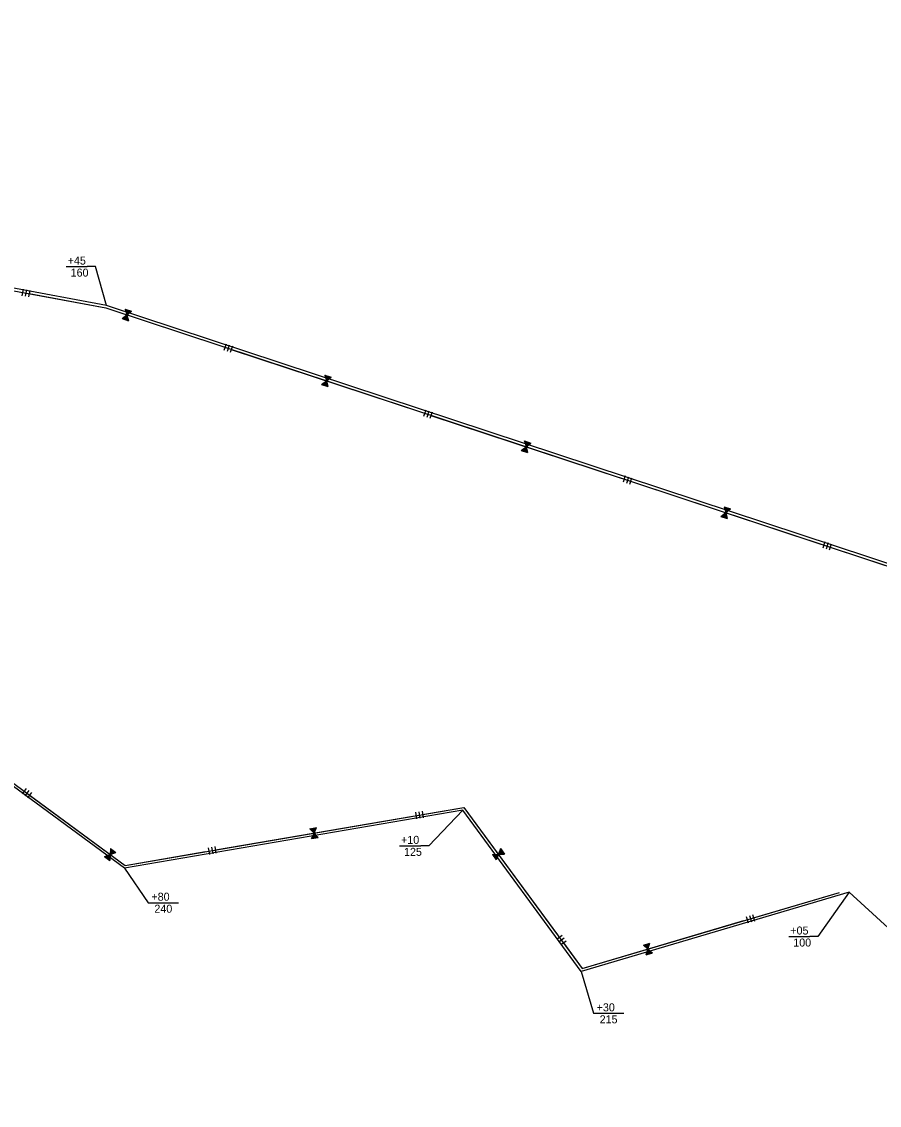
# Model space of a CAD drawing. Extents: x 979729 to 993523, y 1834148 to 1845433.
# Drawn here: x 982788 to 983431, y 1837610 to 1838423 of the extents above; entities that cross this region are included whole.
import ezdxf

# ---------------------------------------------------------------- set-up
doc = ezdxf.new("R2010")
doc.units = 0
for name, color, linetype in [('42', 7, 'Continuous'), ('51', 7, 'Continuous'), ('R_Draft', 7, 'Continuous')]:
    doc.layers.add(name, color=color, linetype=linetype)

msp = doc.modelspace()

# ---------------------------------------------------------------- linework, layer by layer
at = {"layer": '42'}
for p, q in [((982490.19, 1838275.5), (982851.26, 1838208.07)), ((982789.31, 1838222.19), (982788.4, 1838217.27)), ((982791.77, 1838221.73), (982790.85, 1838216.81)), ((982794.23, 1838221.27), (982793.31, 1838216.35)), ((982851.26, 1838208.07), (983611.03, 1837957.02)), ((982865.74, 1838207.24), (982866.94, 1838202.89)), ((982863.39, 1838200.12), (982866.94, 1838202.89)), ((982863.46, 1838200.15), (982863.48, 1838200.09)), ((982863.68, 1838200.3), (982863.77, 1838199.99)), ((982863.89, 1838200.48), (982864.05, 1838199.9)), ((982864.11, 1838200.63), (982864.34, 1838199.8)), ((982864.32, 1838200.82), (982864.62, 1838199.71)), ((982864.52, 1838201), (982864.91, 1838199.62)), ((982864.74, 1838201.15), (982865.19, 1838199.52)), ((982864.98, 1838201.23), (982865.43, 1838199.59)), ((982865.18, 1838201.46), (982865.76, 1838199.33)), ((982865.4, 1838201.6), (982866.05, 1838199.24)), ((982865.6, 1838201.82), (982866.33, 1838199.14)), ((982865.78, 1838207.17), (982865.83, 1838207.21)), ((982865.82, 1838201.94), (982866.62, 1838199.05)), ((982865.87, 1838206.92), (982866.12, 1838207.11)), ((982865.93, 1838206.65), (982866.4, 1838207.02)), ((982866.01, 1838206.4), (982866.69, 1838206.93)), ((982866.02, 1838202.15), (982866.9, 1838198.96)), ((982866.07, 1838206.12), (982866.97, 1838206.83)), ((982866.13, 1838205.85), (982867.26, 1838206.74)), ((982866.21, 1838205.6), (982867.55, 1838206.64)), ((982866.24, 1838202.3), (982867.19, 1838198.86)), ((982866.35, 1838205.39), (982867.7, 1838206.45)), ((982866.38, 1838205.1), (982868.12, 1838206.45)), ((982866.45, 1838202.48), (982867.47, 1838198.77)), ((982866.47, 1838204.85), (982868.4, 1838206.36)), ((982866.5, 1838204.56), (982868.69, 1838206.27)), ((982866.61, 1838204.33), (982868.97, 1838206.17)), ((982866.65, 1838204.04), (982869.26, 1838206.08)), ((982866.68, 1838202.6), (982867.76, 1838198.67)), ((982866.73, 1838203.79), (982869.54, 1838205.98)), ((982866.79, 1838203.51), (982869.83, 1838205.89)), ((982866.88, 1838202.82), (982868.04, 1838198.58)), ((982866.9, 1838203.28), (982870.11, 1838205.79)), ((982866.94, 1838202.99), (982870.4, 1838205.7)), ((982866.94, 1838202.89), (982870.49, 1838205.67)), ((982866.94, 1838202.89), (982868.14, 1838198.55)), ((982941.31, 1838180.95), (982939.74, 1838176.2)), ((982943.69, 1838180.17), (982942.12, 1838175.42)), ((982946.06, 1838179.38), (982944.49, 1838174.63)), ((983012.94, 1838150.7), (983016.49, 1838153.48)), ((983013.01, 1838150.73), (983013.03, 1838150.67)), ((983013.23, 1838150.88), (983013.31, 1838150.58)), ((983013.44, 1838151.07), (983013.6, 1838150.48)), ((983013.66, 1838151.21), (983013.88, 1838150.39)), ((983013.86, 1838151.4), (983014.17, 1838150.29)), ((983014.07, 1838151.59), (983014.45, 1838150.2)), ((983014.29, 1838151.73), (983014.74, 1838150.11)), ((983014.53, 1838151.82), (983014.98, 1838150.17)), ((983014.72, 1838152.04), (983015.31, 1838149.92)), ((983014.94, 1838152.19), (983015.6, 1838149.82)), ((983015.14, 1838152.4), (983015.88, 1838149.73)), ((983015.29, 1838157.82), (983016.49, 1838153.48)), ((983015.33, 1838157.75), (983015.38, 1838157.79)), ((983015.37, 1838152.52), (983016.17, 1838149.63)), ((983015.42, 1838157.5), (983015.67, 1838157.7)), ((983015.47, 1838157.23), (983015.95, 1838157.6)), ((983015.56, 1838156.98), (983016.24, 1838157.51)), ((983015.57, 1838152.73), (983016.45, 1838149.54)), ((983015.62, 1838156.71), (983016.52, 1838157.42)), ((983015.67, 1838156.44), (983016.81, 1838157.32)), ((983015.76, 1838156.19), (983017.09, 1838157.23)), ((983015.79, 1838152.88), (983016.74, 1838149.45)), ((983015.9, 1838155.98), (983017.25, 1838157.03)), ((983015.93, 1838155.68), (983017.66, 1838157.04)), ((983016, 1838153.07), (983017.02, 1838149.35)), ((983016.02, 1838155.43), (983017.95, 1838156.94)), ((983016.05, 1838155.14), (983018.23, 1838156.85)), ((983016.16, 1838154.91), (983018.52, 1838156.76)), ((983016.19, 1838154.62), (983018.8, 1838156.66)), ((983016.22, 1838153.19), (983017.31, 1838149.26)), ((983016.28, 1838154.37), (983019.09, 1838156.57)), ((983016.34, 1838154.1), (983019.37, 1838156.47)), ((983016.42, 1838153.4), (983017.59, 1838149.16)), ((983016.45, 1838153.87), (983019.66, 1838156.38)), ((983016.48, 1838153.58), (983019.94, 1838156.28)), ((983016.49, 1838153.48), (983020.04, 1838156.25)), ((983016.49, 1838153.48), (983017.69, 1838149.13)), ((983090.86, 1838131.53), (983089.29, 1838126.79)), ((983093.23, 1838130.75), (983091.67, 1838126)), ((983095.61, 1838129.97), (983094.04, 1838125.22)), ((983162.49, 1838101.28), (983166.04, 1838104.06)), ((983162.98, 1838101.65), (983163.15, 1838101.07)), ((983163.2, 1838101.8), (983163.43, 1838100.97)), ((983163.41, 1838101.99), (983163.72, 1838100.88)), ((983163.62, 1838102.17), (983164, 1838100.78)), ((983163.84, 1838102.32), (983164.29, 1838100.69)), ((983164.07, 1838102.4), (983164.53, 1838100.76)), ((983164.27, 1838102.62), (983164.86, 1838100.5)), ((983164.49, 1838102.77), (983165.14, 1838100.41)), ((983164.69, 1838102.99), (983165.43, 1838100.31)), ((983164.84, 1838108.41), (983166.04, 1838104.06)), ((983164.88, 1838108.34), (983164.93, 1838108.38)), ((983164.92, 1838103.11), (983165.71, 1838100.22)), ((983164.96, 1838108.09), (983165.21, 1838108.28)), ((983165.02, 1838107.81), (983165.5, 1838108.19)), ((983165.11, 1838107.57), (983165.78, 1838108.09)), ((983165.12, 1838103.32), (983166, 1838100.12)), ((983165.16, 1838107.29), (983166.07, 1838108)), ((983165.22, 1838107.02), (983166.35, 1838107.91)), ((983165.31, 1838106.77), (983166.64, 1838107.81)), ((983165.34, 1838103.47), (983166.28, 1838100.03)), ((983165.45, 1838106.56), (983166.79, 1838107.61)), ((983165.47, 1838106.27), (983167.21, 1838107.62)), ((983165.54, 1838103.65), (983166.57, 1838099.94)), ((983165.56, 1838106.02), (983167.5, 1838107.53)), ((983165.6, 1838105.73), (983167.78, 1838107.43)), ((983165.71, 1838105.5), (983168.07, 1838107.34)), ((983165.74, 1838105.2), (983168.35, 1838107.25)), ((983165.77, 1838103.77), (983166.85, 1838099.84)), ((983165.83, 1838104.96), (983168.64, 1838107.15)), ((983165.88, 1838104.68), (983168.92, 1838107.06)), ((983165.97, 1838103.99), (983167.14, 1838099.75)), ((983165.99, 1838104.45), (983169.21, 1838106.96)), ((983166.03, 1838104.16), (983169.49, 1838106.87)), ((983166.04, 1838104.06), (983169.59, 1838106.84)), ((983166.04, 1838104.06), (983167.23, 1838099.72)), ((983162.56, 1838101.32), (983162.57, 1838101.26)), ((983162.78, 1838101.47), (983162.86, 1838101.16)), ((983240.41, 1838082.12), (983238.84, 1838077.37)), ((983242.78, 1838081.33), (983241.21, 1838076.59)), ((983245.15, 1838080.55), (983243.59, 1838075.8)), ((983312.03, 1838051.87), (983315.58, 1838054.65)), ((983313.38, 1838052.9), (983313.83, 1838051.27)), ((983313.62, 1838052.99), (983314.07, 1838051.34)), ((983313.82, 1838053.21), (983314.4, 1838051.09)), ((983314.04, 1838053.36), (983314.69, 1838050.99)), ((983314.24, 1838053.57), (983314.97, 1838050.9)), ((983314.39, 1838058.99), (983315.58, 1838054.65)), ((983314.42, 1838058.92), (983314.47, 1838058.96)), ((983314.47, 1838053.69), (983315.26, 1838050.8)), ((983314.51, 1838058.67), (983314.76, 1838058.87)), ((983314.57, 1838058.4), (983315.05, 1838058.77)), ((983314.66, 1838058.15), (983315.33, 1838058.68)), ((983314.67, 1838053.9), (983315.55, 1838050.71)), ((983314.71, 1838057.88), (983315.62, 1838058.58)), ((983314.77, 1838057.6), (983315.9, 1838058.49)), ((983314.86, 1838057.36), (983316.19, 1838058.4)), ((983314.88, 1838054.05), (983315.83, 1838050.61)), ((983314.99, 1838057.15), (983316.34, 1838058.2)), ((983315.02, 1838056.85), (983316.76, 1838058.21)), ((983315.09, 1838054.24), (983316.12, 1838050.52)), ((983315.11, 1838056.6), (983317.04, 1838058.11)), ((983315.14, 1838056.31), (983317.33, 1838058.02)), ((983315.25, 1838056.08), (983317.61, 1838057.92)), ((983315.29, 1838055.79), (983317.9, 1838057.83)), ((983315.32, 1838054.36), (983316.4, 1838050.43)), ((983315.38, 1838055.54), (983318.18, 1838057.74)), ((983315.43, 1838055.27), (983318.47, 1838057.64)), ((983315.52, 1838054.57), (983316.69, 1838050.33)), ((983315.54, 1838055.04), (983318.75, 1838057.55)), ((983315.58, 1838054.75), (983319.04, 1838057.45)), ((983315.58, 1838054.65), (983319.13, 1838057.42)), ((983315.58, 1838054.65), (983316.78, 1838050.3)), ((983312.1, 1838051.9), (983312.12, 1838051.84)), ((983312.32, 1838052.05), (983312.41, 1838051.75)), ((983312.53, 1838052.24), (983312.69, 1838051.65)), ((983312.75, 1838052.38), (983312.98, 1838051.56)), ((983312.96, 1838052.57), (983313.26, 1838051.46)), ((983313.17, 1838052.75), (983313.55, 1838051.37)), ((983389.95, 1838032.7), (983388.39, 1838027.96)), ((983392.33, 1838031.92), (983390.76, 1838027.17)), ((983394.7, 1838031.13), (983393.13, 1838026.39)), ((982600.97, 1837985.09), (982865.65, 1837790.18)), ((982791.59, 1837847.82), (982788.62, 1837843.79)), ((982793.6, 1837846.34), (982790.64, 1837842.31)), ((982795.62, 1837844.86), (982792.65, 1837840.83)), ((982865.65, 1837790.18), (983119.48, 1837833.71)), ((983119.48, 1837833.71), (983208.17, 1837712.96)), ((983083.23, 1837830.03), (983084.07, 1837825.1)), ((983085.69, 1837830.45), (983086.54, 1837825.53)), ((983088.15, 1837830.88), (983089, 1837825.95)), ((983004.17, 1837817.74), (983007.26, 1837814.47)), ((983004.23, 1837817.7), (983004.26, 1837817.75)), ((983004.43, 1837817.52), (983004.55, 1837817.81)), ((983004.6, 1837817.3), (983004.85, 1837817.86)), ((983004.8, 1837817.12), (983005.15, 1837817.91)), ((983004.98, 1837816.91), (983005.44, 1837817.96)), ((983005.16, 1837816.7), (983005.74, 1837818.01)), ((983005.35, 1837816.52), (983006.04, 1837818.06)), ((983005.57, 1837816.4), (983006.26, 1837817.96)), ((983005.73, 1837816.15), (983006.63, 1837818.16)), ((983005.93, 1837815.97), (983006.92, 1837818.21)), ((983006.09, 1837815.73), (983007.22, 1837818.26)), ((983006.3, 1837815.58), (983007.52, 1837818.31)), ((983006.47, 1837815.34), (983007.81, 1837818.36)), ((983006.66, 1837815.16), (983008.11, 1837818.42)), ((983006.84, 1837814.94), (983008.4, 1837818.47)), ((983007.04, 1837814.79), (983008.7, 1837818.52)), ((983007.21, 1837814.55), (983009, 1837818.57)), ((983007.26, 1837814.47), (983009.09, 1837818.58)), ((983005.43, 1837810.35), (983007.26, 1837814.47)), ((983005.48, 1837810.41), (983005.53, 1837810.36)), ((983005.61, 1837810.64), (983005.82, 1837810.41)), ((983005.7, 1837810.91), (983006.12, 1837810.46)), ((983005.83, 1837811.14), (983006.42, 1837810.52)), ((983005.92, 1837811.4), (983006.71, 1837810.57)), ((983006.02, 1837811.66), (983007.01, 1837810.62)), ((983006.14, 1837811.9), (983007.3, 1837810.67)), ((983006.31, 1837812.08), (983007.48, 1837810.84)), ((983006.38, 1837812.37), (983007.9, 1837810.77)), ((983006.51, 1837812.6), (983008.19, 1837810.82)), ((983006.58, 1837812.88), (983008.49, 1837810.87)), ((983006.73, 1837813.1), (983008.78, 1837810.92)), ((983006.8, 1837813.38), (983009.08, 1837810.97)), ((983006.93, 1837813.61), (983009.38, 1837811.02)), ((983007.02, 1837813.87), (983009.67, 1837811.07)), ((983007.17, 1837814.09), (983009.97, 1837811.12)), ((983007.24, 1837814.37), (983010.26, 1837811.18)), ((983007.26, 1837814.47), (983010.36, 1837811.19)), ((982854.73, 1837802.87), (982854.52, 1837798.37)), ((982854.67, 1837801.44), (982856.02, 1837801.92)), ((982854.67, 1837801.17), (982856.26, 1837801.75)), ((982854.67, 1837800.64), (982856.75, 1837801.39)), ((982854.68, 1837800.38), (982856.99, 1837801.21)), ((982854.7, 1837801.71), (982855.78, 1837802.1)), ((982854.72, 1837802.25), (982855.29, 1837802.46)), ((982854.73, 1837801.99), (982855.54, 1837802.28)), ((982854.74, 1837800.93), (982856.35, 1837801.51)), ((982854.75, 1837802.79), (982854.81, 1837802.82)), ((982854.76, 1837802.53), (982855.05, 1837802.64)), ((982927.99, 1837803.41), (982928.84, 1837798.48)), ((982930.46, 1837803.83), (982931.3, 1837798.9)), ((982932.92, 1837804.25), (982933.77, 1837799.32)), ((983146.86, 1837802.77), (983145.32, 1837798.53)), ((983146.29, 1837801.16), (983147.98, 1837801.24)), ((983146.37, 1837801.42), (983147.8, 1837801.48)), ((983146.48, 1837801.67), (983147.63, 1837801.73)), ((983146.59, 1837801.93), (983147.45, 1837801.97)), ((983146.66, 1837802.18), (983147.27, 1837802.21)), ((983146.78, 1837802.44), (983147.09, 1837802.45)), ((983146.85, 1837802.69), (983146.91, 1837802.69)), ((982850.29, 1837796.83), (982854.52, 1837798.37)), ((982850.37, 1837796.84), (982850.36, 1837796.78)), ((982850.62, 1837796.91), (982850.6, 1837796.6)), ((982850.87, 1837797.03), (982850.85, 1837796.42)), ((982851.13, 1837797.1), (982851.09, 1837796.24)), ((982851.38, 1837797.21), (982851.33, 1837796.06)), ((982851.64, 1837797.32), (982851.57, 1837795.89)), ((982851.89, 1837797.4), (982851.81, 1837795.71)), ((982852.14, 1837797.4), (982852.06, 1837795.7)), ((982852.4, 1837797.55), (982852.3, 1837795.35)), ((982852.65, 1837797.62), (982852.54, 1837795.17)), ((982852.91, 1837797.76), (982852.78, 1837795)), ((982853.16, 1837797.81), (982853.02, 1837794.82)), ((982853.42, 1837797.95), (982853.27, 1837794.64)), ((982853.67, 1837798.02), (982853.51, 1837794.46)), ((982853.93, 1837798.13), (982853.75, 1837794.28)), ((982854.18, 1837798.18), (982853.99, 1837794.1)), ((982854.44, 1837798.32), (982854.23, 1837793.93)), ((982854.52, 1837798.37), (982854.31, 1837793.87)), ((982854.52, 1837798.37), (982858.76, 1837799.91)), ((982854.55, 1837798.47), (982858.68, 1837799.97)), ((982854.57, 1837799.01), (982858.2, 1837800.32)), ((982854.6, 1837799.55), (982857.71, 1837800.68)), ((982854.61, 1837799.29), (982857.95, 1837800.5)), ((982854.61, 1837798.75), (982858.44, 1837800.14)), ((982854.62, 1837800.09), (982857.23, 1837801.03)), ((982854.66, 1837799.83), (982857.47, 1837800.86)), ((983140.81, 1837798.33), (983145.32, 1837798.53)), ((983140.89, 1837798.32), (983140.87, 1837798.25)), ((983141.16, 1837798.31), (983141.05, 1837798.01)), ((983141.43, 1837798.34), (983141.22, 1837797.77)), ((983141.7, 1837798.33), (983141.4, 1837797.53)), ((983141.97, 1837798.36), (983141.58, 1837797.29)), ((983142.25, 1837798.39), (983141.76, 1837797.04)), ((983142.51, 1837798.39), (983141.94, 1837796.8)), ((983142.76, 1837798.32), (983142.17, 1837796.72)), ((983143.05, 1837798.39), (983142.29, 1837796.32)), ((983143.31, 1837798.38), (983142.47, 1837796.07)), ((983143.6, 1837798.44), (983142.65, 1837795.83)), ((983143.85, 1837798.4), (983142.83, 1837795.59)), ((983144.14, 1837798.46), (983143, 1837795.35)), ((983144.4, 1837798.45), (983143.18, 1837795.11)), ((983144.68, 1837798.49), (983143.36, 1837794.86)), ((983144.93, 1837798.45), (983143.54, 1837794.62)), ((983145.22, 1837798.51), (983143.71, 1837794.38)), ((983145.32, 1837798.53), (983143.77, 1837794.3)), ((983145.32, 1837798.53), (983149.82, 1837798.74)), ((983145.37, 1837798.62), (983149.76, 1837798.82)), ((983145.51, 1837798.88), (983149.58, 1837799.06)), ((983145.55, 1837799.13), (983149.4, 1837799.3)), ((983145.67, 1837799.38), (983149.23, 1837799.55)), ((983145.74, 1837799.64), (983149.05, 1837799.79)), ((983145.88, 1837799.89), (983148.87, 1837800.03)), ((983145.92, 1837800.15), (983148.69, 1837800.27)), ((983146.06, 1837800.4), (983148.51, 1837800.51)), ((983146.14, 1837800.66), (983148.34, 1837800.76)), ((983146.29, 1837800.91), (983147.99, 1837800.99)), ((983208.17, 1837712.96), (983400.86, 1837769.95)), ((983333.39, 1837752.6), (983334.81, 1837747.81)), ((983335.79, 1837753.31), (983337.21, 1837748.52)), ((983330.99, 1837751.89), (983332.41, 1837747.1)), ((983193.21, 1837737.55), (983189.18, 1837734.59)), ((983194.69, 1837735.54), (983190.66, 1837732.58)), ((983196.17, 1837733.52), (983192.14, 1837730.56)), ((983253.92, 1837730.4), (983257.38, 1837727.51)), ((983253.99, 1837730.37), (983254.01, 1837730.43)), ((983254.21, 1837730.21), (983254.3, 1837730.51)), ((983254.41, 1837730.02), (983254.59, 1837730.6)), ((983254.62, 1837729.86), (983254.88, 1837730.68)), ((983254.83, 1837729.67), (983255.17, 1837730.77)), ((983255.03, 1837729.48), (983255.45, 1837730.85)), ((983255.24, 1837729.33), (983255.74, 1837730.94)), ((983255.47, 1837729.23), (983255.98, 1837730.87)), ((983255.67, 1837729), (983256.32, 1837731.11)), ((983255.88, 1837728.85), (983256.61, 1837731.19)), ((983256.07, 1837728.63), (983256.89, 1837731.28)), ((983256.3, 1837728.5), (983257.18, 1837731.36)), ((983256.49, 1837728.28), (983257.47, 1837731.45)), ((983256.7, 1837728.13), (983257.76, 1837731.53)), ((983256.91, 1837727.94), (983258.05, 1837731.62)), ((983257.13, 1837727.81), (983258.33, 1837731.71)), ((983257.32, 1837727.59), (983258.62, 1837731.79)), ((983257.38, 1837727.51), (983258.72, 1837731.82)), ((983256.05, 1837723.21), (983257.38, 1837727.51)), ((983256.09, 1837723.28), (983256.14, 1837723.24)), ((983256.19, 1837723.52), (983256.43, 1837723.32)), ((983256.25, 1837723.79), (983256.72, 1837723.41)), ((983256.35, 1837724.04), (983257.01, 1837723.49)), ((983256.41, 1837724.31), (983257.29, 1837723.58)), ((983256.48, 1837724.58), (983257.58, 1837723.66)), ((983256.57, 1837724.83), (983257.87, 1837723.75)), ((983256.72, 1837725.03), (983258.03, 1837723.94)), ((983256.75, 1837725.33), (983258.45, 1837723.92)), ((983256.85, 1837725.57), (983258.73, 1837724)), ((983256.89, 1837725.86), (983259.02, 1837724.09)), ((983257.01, 1837726.09), (983259.31, 1837724.17)), ((983257.05, 1837726.38), (983259.6, 1837724.26)), ((983257.15, 1837726.63), (983259.89, 1837724.34)), ((983257.21, 1837726.9), (983260.17, 1837724.43)), ((983257.33, 1837727.12), (983260.46, 1837724.51)), ((983257.37, 1837727.41), (983260.75, 1837724.6)), ((983257.38, 1837727.51), (983260.85, 1837724.63))]:
    msp.add_line(p, q, dxfattribs=at)
for points in [[(982793.77, 1838218.81), (982851.26, 1838208.07), (982938.16, 1838179.36)], [(982865.74, 1838207.24), (982870.49, 1838205.67)], [(982863.39, 1838200.12), (982868.14, 1838198.55)], [(982945.28, 1838177.01), (983087.7, 1838129.95)], [(983012.94, 1838150.7), (983017.69, 1838149.13)], [(983015.29, 1838157.82), (983020.04, 1838156.25)], [(983094.82, 1838127.59), (983237.25, 1838080.53)], [(983164.84, 1838108.41), (983169.59, 1838106.84)], [(983162.49, 1838101.28), (983167.23, 1838099.72)], [(983244.37, 1838078.18), (983386.8, 1838031.11)], [(983314.39, 1838058.99), (983319.13, 1838057.42)], [(983312.03, 1838051.87), (983316.78, 1838050.3)], [(983393.92, 1838028.76), (983536.34, 1837981.7)], [(982794.13, 1837842.84), (982865.65, 1837790.18), (982925.95, 1837800.52)], [(983088.58, 1837828.41), (983119.48, 1837833.71), (983189.72, 1837738.09)], [(982933.34, 1837801.79), (983081.18, 1837827.15)], [(983004.17, 1837817.74), (983009.09, 1837818.58)], [(983005.43, 1837810.35), (983010.36, 1837811.19)], [(982854.73, 1837802.87), (982858.76, 1837799.91)], [(983146.86, 1837802.77), (983149.82, 1837798.74)], [(982850.29, 1837796.83), (982854.31, 1837793.87)], [(983140.81, 1837798.33), (983143.77, 1837794.3)], [(983336.5, 1837750.92), (983400.86, 1837769.95)], [(983194.16, 1837732.04), (983208.17, 1837712.96), (983329.3, 1837748.79)], [(983253.92, 1837730.4), (983258.72, 1837731.82)], [(983256.05, 1837723.21), (983260.85, 1837724.63)]]:
    msp.add_lwpolyline(points, dxfattribs=at)
at = {"layer": '51'}
for points in [[(983839.63, 1837883.59), (982851.76, 1838210.02), (982490.82, 1838277.42), (982183.3, 1838422.69)], [(983832.14, 1837610.35), (983652.57, 1837707.14), (983510.47, 1837676.41), (983408.2, 1837770.04), (983207.39, 1837710.64), (983118.6, 1837831.53), (982865.15, 1837788.06), (982600.28, 1837983.11), (982196.59, 1837995.54), (982113.58, 1838135.58), (981690.98, 1838258.2), (981584.78, 1838227.65)]]:
    msp.add_lwpolyline(points, dxfattribs=at)
at = {"layer": 'R_Draft'}
for p, q in [((982821.61, 1838239.08), (982837.41, 1838239.08)), ((983071.34, 1837804.86), (983087.14, 1837804.86)), ((982889.05, 1837762.24), (982905.81, 1837762.24)), ((983362.91, 1837736.88), (983378.71, 1837736.88)), ((983222.55, 1837679.31), (983239.31, 1837679.31))]:
    msp.add_line(p, q, dxfattribs=at)
for points in [[(982851.76, 1838210.02), (982843.41, 1838239.08), (982837.41, 1838239.08)], [(983118.6, 1837831.53), (983093.14, 1837804.86), (983087.14, 1837804.86)], [(982865.15, 1837788.06), (982883.05, 1837762.24), (982889.05, 1837762.24)], [(983408.2, 1837770.04), (983384.71, 1837736.88), (983378.71, 1837736.88)], [(983207.39, 1837710.64), (983216.55, 1837679.31), (983222.55, 1837679.31)]]:
    msp.add_lwpolyline(points, dxfattribs=at)

# ---------------------------------------------------------------- texts
for s, p in [('+45', (982822.69, 1838240.58)), (' 160', (982822.69, 1838231.58)), ('+10', (983072.42, 1837806.36)), (' 125', (983072.42, 1837797.36)), ('+80', (982885.43, 1837763.74)), (' 240', (982885.43, 1837754.74)), ('+05', (983363.99, 1837738.38)), (' 100', (983363.99, 1837729.38)), ('+30', (983218.93, 1837680.81)), (' 215', (983218.93, 1837671.81))]:
    msp.add_text(s, height=6, rotation=360, dxfattribs=at).set_placement(p)

doc.saveas('drawing.dxf')
